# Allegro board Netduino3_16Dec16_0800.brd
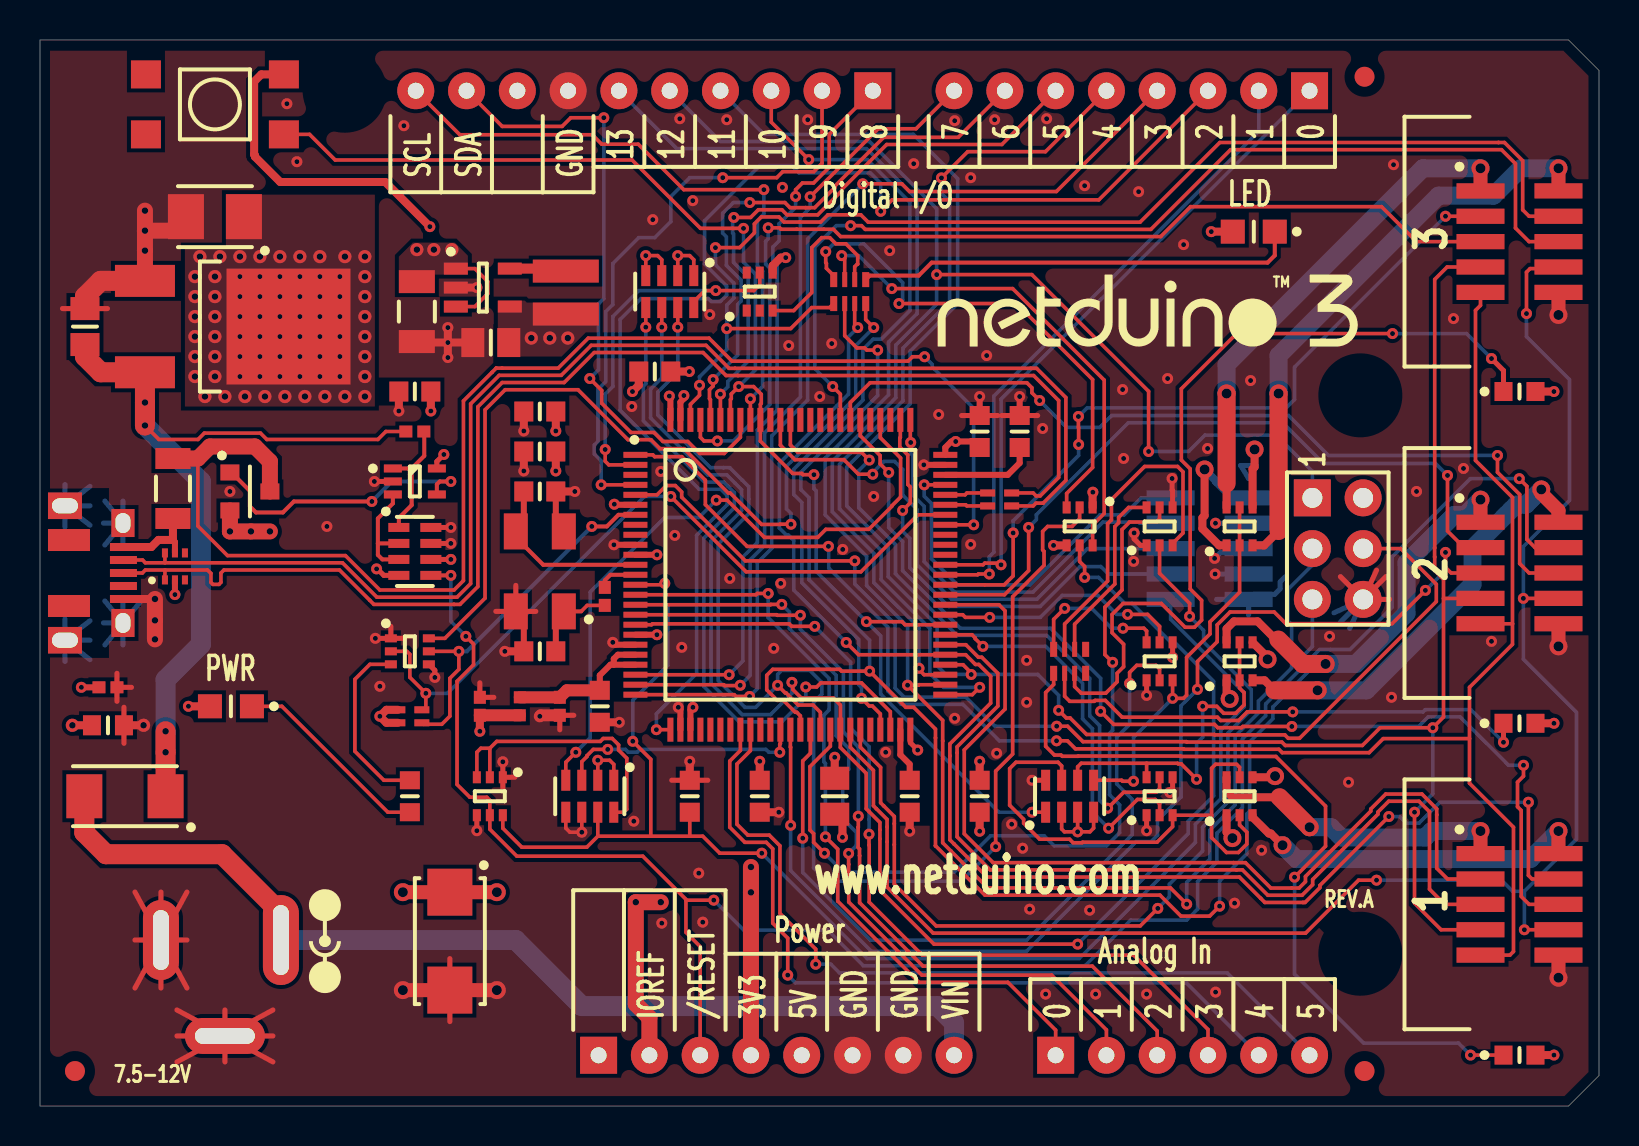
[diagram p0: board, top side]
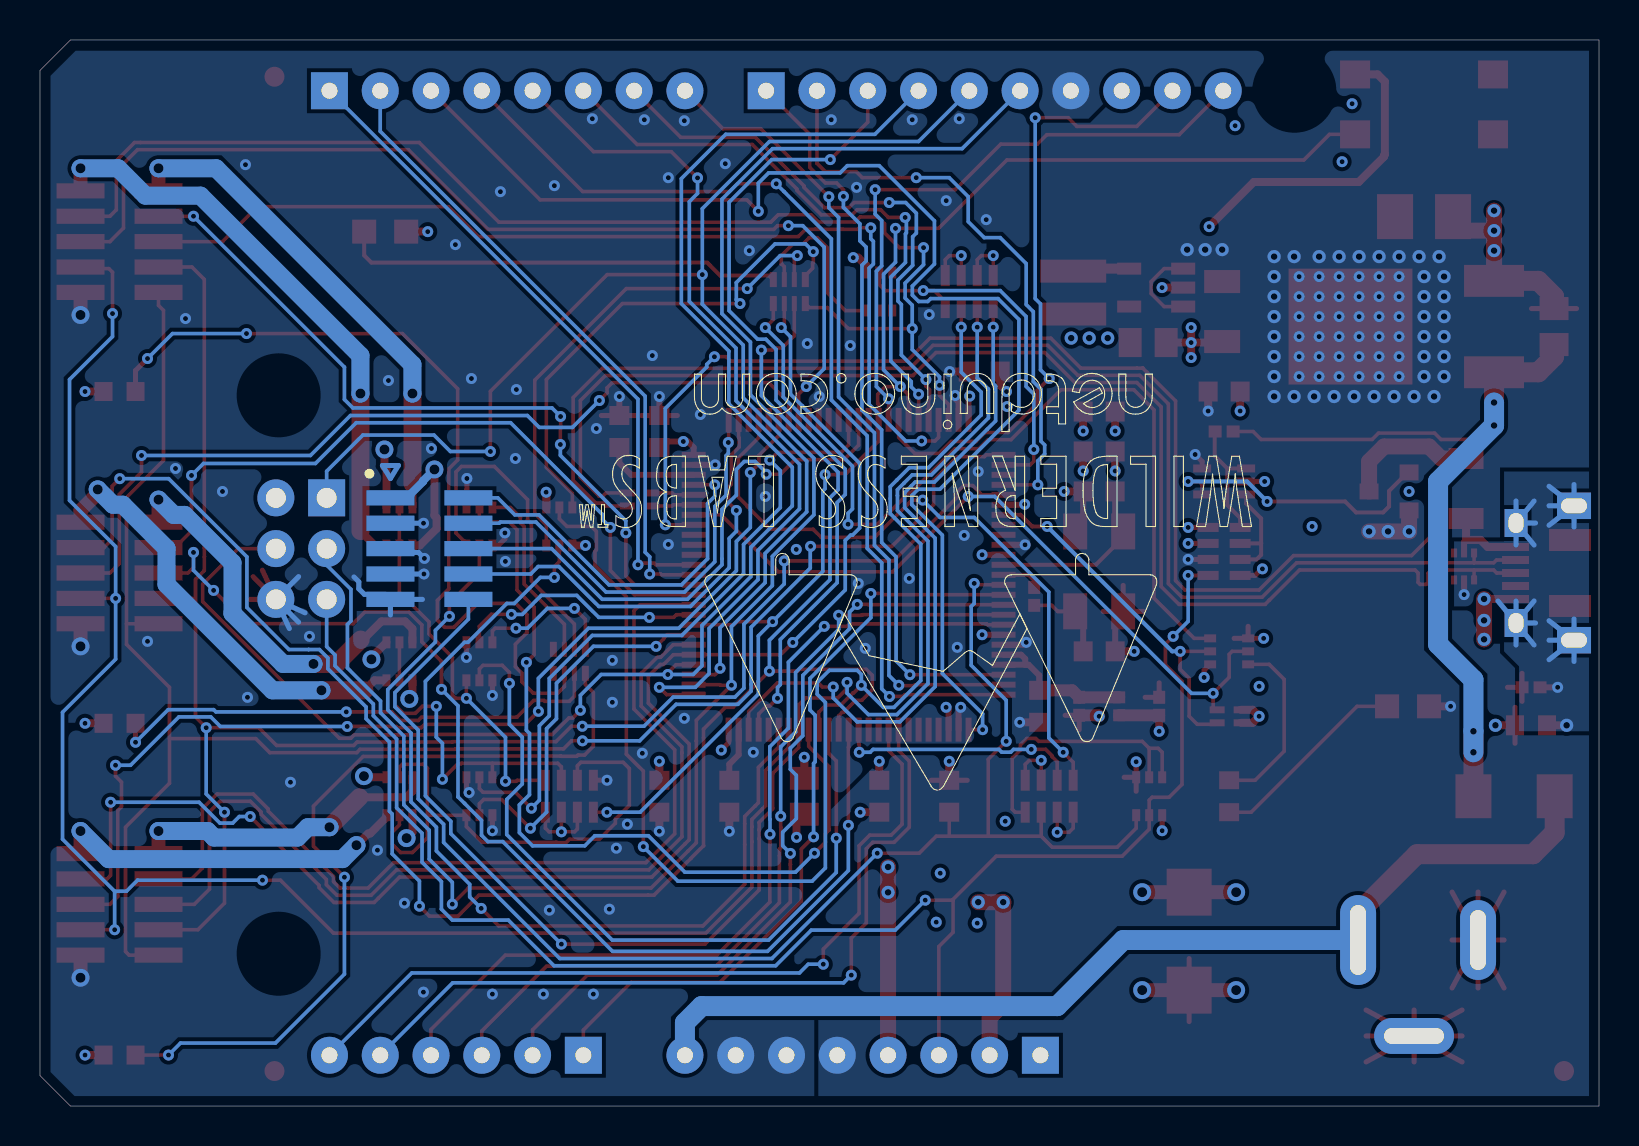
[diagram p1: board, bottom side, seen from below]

Outline 77.98 x 53.34 mm; copper layers: TOP, L2-GND, L3-PWR, BOTTOM. Coordinates in mm from the lower left corner of the outline.
Outline path: 0,0 0,53.34 76.45,53.34 77.98,51.82 77.98,1.52 76.45,0 0,0

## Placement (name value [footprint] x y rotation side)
C1  22uF  [CAPC3216X180N]  18.85 39.75 270 top
C2  10uF  [CAPC2012X125N]  2.25 39 90 top
C4  22uF  [CAPC2012X125N]  22.55 38.2 180 top
C5  0.1uF  [CAPC1608X90N]  28 20 270 top
C6  0.1uF  [CAPC1608X90N]  18.75 35.75 180 top
C10  0.1uF  [CAPC1608X90N]  25 32.75 180 top
C11  0.1uF  [CAPC1608X90N]  36 15.5 270 top
C12  0.1uF  [CAPC1608X90N]  47 15.5 270 top
C13  0.1uF  [CAPC1608X90N]  47 33.75 90 top
C14  0.1uF  [CAPC1608X90N]  30.75 36.75 0 top
C16  2.2uF  [CAPC1608X90N]  49 33.75 90 top
C17  2.2uF  [CAPC1608X90N]  43.5 15.5 270 top
C18  18pF  [CAPC1608X90N]  25 30.75 0 top
C19  18pF  [CAPC1608X90N]  25 22.75 180 top
C20  4.7nF  [CAPC1005X55N]  3.4 20.95 180 top
C21  100uF  [CAPMP6032X280N]  20.5 8.25 270 top
C42  22uF  [CAPC2012X125N]  39.75 15.5 270 top
C43  47uF  [F931A476MBA]  8.75 44.5 180 top
C44  1uF  [CAPC1005X55N]  26 20 270 top
C45  1uF  [CAPC1005X55N]  22 20 90 top
C46  0.1uF  [CAPC1608X90N]  25 34.75 180 top
C47  0.1uF  [CAPC1608X90N]  32.5 15.5 90 top
D1  WHITE  [LEDC2012X110N]  9.55 20 180 top
D2  BLUE  [LEDC2012X110N]  60.71 43.75 180 top
D3  SS15E-TP  [SS15-TP]  4.25 15.5 180 top
D4  -  [SP3003-04XTG]  6.75 27 90 top
D5  BLUE  [LEDC1608X80N]  74 2.55 0 top
D6  BLUE  [LEDC1608X80N]  74 19.15 0 top
D7  BLUE  [LEDC1608X80N]  74 35.75 0 top
F1  MF-NSMF075-2  [RESC3216X100N]  6.65 30.9 90 top
F2  -  [FID_1-00_X_2-00]  1.75 1.75 0 top
F3  -  [FID_1-00_X_2-00]  66.25 1.75 0 top
F4  -  [FID_1-00_X_2-00]  66.25 51.5 0 top
J1  ADC-043A-1  [ADC-002A-1]  -1.75 8.31 90 top
J2  HDR100IMP08F-G-V-TH-BLUE  [HDR100IMP08F-G-V-TH]  63.5 50.8 180 top
J3  HDR100IMP08F-G-V-TH-BLUE  [HDR100IMP10F-G-V-TH]  41.66 50.8 180 top
J4  HDR100IMP08F-G-V-TH-BLUE  [HDR100IMP06F-G-V-TH]  50.8 2.54 0 top
J5  -  [DX4R005JJ2R1800]  0 26.67 270 top
J6  HDR100IMP08F-G-V-TH-BLUE  [HDR100IMP08F-G-V-TH]  27.94 2.54 0 top
J7  -  [67996-206HLF]  63.64 30.43 270 top
J8  -  [MINI_JTAG_SMD]  58.5 27.89 180 bottom
J10  HDR050IDC10MS2-G-V-SM-BLUE  [20021521-00010T1LF]  74 10.09 0 top
J11  HDR050IDC10MS2-G-V-SM-BLUE  [20021521-00010T1LF]  74 26.67 0 top
J12  HDR050IDC10MS2-G-V-SM-BLUE  [20021521-00010T1LF]  74 43.25 0 top
L1  2.2uH  [LQH3NPN2R2NM0L]  26.3 40.7 270 top
L2  BEAD FERRITE/SM  [INDC1005X55N]  24 20 270 top
MT1  -  [MTG320H420NP_720KO]  15.24 50.8 0 top
MT2  -  [MTG320H420NP_720KO]  66.04 35.56 0 top
MT3  -  [MTG320H420NP_720KO]  66.04 7.62 0 top
NOREF  -  []  44.9 38 0 top
NOREF#2  -  []  14.25 8.25 90 top
NOREF#3  -  []  0 0 90 top
NOREF#4  -  []  0 53.34 0 top
Q1  -  [MUN5215DW1T1G]  18.5 22.75 0 top
Q2  -  [MUN5215DW1T1G]  22.5 15.5 270 top
Q3  -  [NTR4101PT1G]  10.5 30.75 0 top
Q4  -  [NTJD4152PT1G]  36 40.75 90 top
Q5  -  [NTJD4152PT1G]  60 15.5 90 top
Q6  -  [MUN5215DW1T1G]  56 15.5 90 top
Q7  -  [NTJD4152PT1G]  60 22.25 90 top
Q8  -  [NTJD4152PT1G]  52 29 270 top
Q9  -  [NTJD4152PT1G]  60 29 90 top
Q10  -  [MUN5215DW1T1G]  56 22.25 90 top
Q11  -  [MUN5215DW1T1G]  56 29 90 top
R1  1K  [RESCAV50P80X160X60-8N]  40.5 40.75 270 top
R3  1.5K  [RESC1608]  18.5 15.5 90 top
R4  10K  [RESCAV80P160X320X70-8N]  18.75 27.75 0 top
R5  10K  [RESCAV80P160X320X70-8N]  27.5 15.5 270 top
R6  15.4K  [CAPC1005X55N]  18.75 33.75 0 top
R7  390  [CAPC1005X55N]  28.25 25.5 90 top
R8  100K  [EXB24V]  18.5 19.5 0 top
R9  22  [EXB24V]  48 30.35 180 top
R10  1M  [RESC1608]  3.4 19.05 180 top
R12  10K  [RESCAV80P160X320X70-8N]  51.5 15.5 90 top
R14  10K  [RESCAV80P160X320X70-8N]  31.5 40.75 270 top
R15  680  [RESCAV50P80X160X60-8N]  51.5 22.25 90 top
SW1  -  [TSXH-2GL]  8.75 50.12 0 top
U1  LM3671MF-3.3/NOPB  [LM3671MF]  22.15 40.95 0 top
U2  -  [TLV1117-50IKVURG3]  5.25 39 0 top
U3  -  [LMV321IDCKR]  18.75 31.25 0 top
U4  STM32F427  [STM32F427VIT6]  37.53 26.58 0 top
Y1  25 Mhz  [ABM3B]  25 26.75 90 top

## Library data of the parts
C1 C2 C4-C6 C10-C14 C16-C21 C42-C47 = C
D1 = LED_2
D2 D5-D7 = LED_1
D3 = D05AZ75_0
D4 = HEADER 6_0
F1 = FUSE
F2-F4 MT1-MT3 = MOUNT_HOLE
J1 = HEADER 3
J2 J6 = HEADER 8
J3 = HEADER 10
J4 = HEADER 6
J5 = HEADER 11_0
J7 = HEADER 6_1
J8 J10-J12 = HEADER 10_2
L1 = L
L2 = BEAD FERRITE/SM
Q1 Q2 = MUN5215DW1T1G_3
Q3 = NDF0610/TO_1
Q4 Q5 Q7-Q9 = NTJD4152PT1G
Q6 Q10 Q11 = MUN5215DW1T1G_0
R1 R4 R5 R12 R14 R15 = RESCAV50P80X160X60-8N
R3 R6 R7 R10 = R
R8 R9 = EXB24V
SW1 = SW PUSHBUTTON-SPST-2_0
U1 = HEADER 5_0
U2 = LM7805/TO_2
U3 = LMV321/SO
U4 = STM32F427_0
Y1 = OSC_XF

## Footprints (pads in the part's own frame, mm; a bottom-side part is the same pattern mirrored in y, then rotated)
67996-206HLF
  rect 1.85x1.85 hole 1: 1(0,0)
  round 1.85 hole 1: 2(0,2.54) 3(2.54,0) 4(2.54,2.54) 5(5.08,0) 6(5.08,2.54)
20021521-00010T1LF
  rect 2.4x0.76 smd: 1(-1.95,2.54) 2(1.95,2.54) 3(-1.95,1.27) 4(1.95,1.27) 5(-1.95,0) 6(1.95,0) 7(-1.95,-1.27) 8(1.95,-1.27) 9(-1.95,-2.54) 10(1.95,-2.54)
ABM3B
  rect 1.8x1.2 smd: 1(-2,-1.2) 2(2,-1.2) 3(2,1.2) 4(-2,1.2)
ADC-002A-1
  oval 4.5x1.8 hole 3.5x0.8: 1(0,-13.8)
  oval 1.8x4 hole 0.8x3: 2(-4.8,-11)
  oval 4x1.8 hole 3x0.8: 3(0,-7.8)
CAPC1005X55N
  rect 0.65x0.6 smd: 1(-0.45,0) 2(0.45,0)
CAPC1608X90N
  rect 0.95x1 smd: 1(-0.8,0) 2(0.8,0)
CAPC2012X125N
  rect 1.15x1.45 smd: 1(-0.9,0) 2(0.9,0)
CAPC3216X180N
  rect 1.15x1.8 smd: 1(-1.5,0) 2(1.5,0)
CAPMP6032X280N
  rect 2.35x2.25 smd: 1(-2.45,0) 2(2.45,0)
DX4R005JJ2R1800
  rect 0.4x1.35 smd: 1(-1.3,4.175) 2(-0.65,4.175) 3(0,4.175) 4(0.65,4.175) 5(1.3,4.175)
  rect 1.4x1.15 hole 1x0.75: 6(-2.5,4.15) 7(2.5,4.15)
  rect 1.325x1.7 hole 0.75x1.3: 8(-3.362,1.25) 11(3.362,1.25)
  rect 1.1x2.1 smd: 9(-1.65,1.45) 10(1.65,1.45)
EXB24V
  rect 0.75x0.35 smd: 1(-0.6,0.325) 2(-0.6,-0.325) 3(0.6,-0.325) 4(0.6,0.325)
F931A476MBA
  rect 1.8x2.25 smd: 1(-1.45,0) 2(1.45,0)
FID_1-00_X_2-00
  round 1 smd: 1(0,0)
HDR100IMP06F-G-V-TH
  rect 1.85x1.85 hole 0.8: 1(0,0)
  round 1.85 hole 0.8: 2(2.54,0) 3(5.08,0) 4(7.62,0) 5(10.16,0) 6(12.7,0)
HDR100IMP08F-G-V-TH
  rect 1.85x1.85 hole 0.8: 1(0,0)
  round 1.85 hole 0.8: 2(2.54,0) 3(5.08,0) 4(7.62,0) 5(10.16,0) 6(12.7,0) 7(15.24,0) 8(17.78,0)
HDR100IMP10F-G-V-TH
  rect 1.85x1.85 hole 0.8: 1(0,0)
  round 1.85 hole 0.8: 2(2.54,0) 3(5.08,0) 4(7.62,0) 5(10.16,0) 6(12.7,0) 7(15.24,0) 8(17.78,0) 9(20.32,0) 10(22.86,0)
INDC1005X55N
  rect 0.6x0.6 smd: 1(-0.45,0) 2(0.45,0)
LEDC1608X80N
  rect 0.899x0.95 smd: A(0.8,0) C(-0.8,0)
LEDC2012X110N
  rect 1.2x1.2 smd: A(1.05,0) C(-1.05,0)
LM3671MF
  rect 1.2x0.6 smd: 1(-1.35,0.95) 2(-1.35,0) 3(-1.35,-0.95) 4(1.35,-0.95) 5(1.35,0.95)
LMV321IDCKR
  rect 0.9x0.4 smd: 1(-1.1,0.65) 2(-1.1,0) 3(-1.1,-0.65) 4(1.1,-0.65) 5(1.1,0.65)
LQH3NPN2R2NM0L
  rect 1.15x3.3 smd: 1(-1.075,0) 2(1.075,0)
MINI_JTAG_SMD
  rect 2.4x0.76 smd: 1(-1.95,2.54) 2(1.95,2.54) 3(-1.95,1.27) 4(1.95,1.27) 5(-1.95,0) 6(1.95,0) 7(-1.95,-1.27) 8(1.95,-1.27) 9(-1.95,-2.54) 10(1.95,-2.54)
MTG320H420NP_720KO
  round 0 hole 3.2 unplated: (0,0)
MUN5215DW1T1G
  rect 0.6x0.4 smd: 1(-0.95,0.65) 2(-0.95,0) 3(-0.95,-0.65) 4(0.95,-0.65) 5(0.95,0) 6(0.95,0.65)
NTJD4152PT1G
  rect 0.6x0.4 smd: 1(-0.95,0.65) 2(-0.95,0) 3(-0.95,-0.65) 4(0.95,-0.65) 5(0.95,0) 6(0.95,0.65)
NTR4101PT1G
  rect 0.95x0.8 smd: 1(-1,0.95) 2(-1,-0.95) 3(1,0)
RESC1608
  rect 0.899x1.001 smd: 1(-0.8,0) 2(0.8,0)
RESC3216X100N
  rect 1.05x1.75 smd: 1(-1.5,0) 2(1.5,0)
RESCAV50P80X160X60-8N
  rect 0.75x0.35 smd: 1(-0.6,0.8) 4(-0.6,-0.8) 5(0.6,-0.8) 8(0.6,0.8)
  rect 0.75x0.25 smd: 2(-0.6,0.25) 3(-0.6,-0.25) 6(0.6,-0.25) 7(0.6,0.25)
RESCAV80P160X320X70-8N
  rect 1.05x0.45 smd: 1(-0.8,1.2) 2(-0.8,0.4) 3(-0.8,-0.4) 4(-0.8,-1.2) 5(0.8,-1.2) 6(0.8,-0.4) 7(0.8,0.4) 8(0.8,1.2)
SP3003-04XTG
  rect 0.45x0.3 smd: 1(-0.675,0.5) 2(-0.675,0) 3(-0.675,-0.5) 4(0.675,-0.5) 5(0.675,0) 6(0.675,0.5)
SS15-TP
  rect 1.8x2.2 smd: A(2.032,0) C(-2.032,0)
STM32F427VIT6
  rect 1.2x0.3 smd: 1(-7.75,6) 2(-7.75,5.5) 3(-7.75,5) 4(-7.75,4.5) 5(-7.75,4) 6(-7.75,3.5) 7(-7.75,3) 8(-7.75,2.5) 9(-7.75,2) 10(-7.75,1.5) 11(-7.75,1) 12(-7.75,0.5) 13(-7.75,0) 14(-7.75,-0.5) 15(-7.75,-1) 16(-7.75,-1.5) 17(-7.75,-2) 18(-7.75,-2.5) 19(-7.75,-3) 20(-7.75,-3.5) 21(-7.75,-4) 22(-7.75,-4.5) 23(-7.75,-5) 24(-7.75,-5.5) 25(-7.75,-6) 51(7.75,-6) 52(7.75,-5.5) 53(7.75,-5) 54(7.75,-4.5) 55(7.75,-4) 56(7.75,-3.5) 57(7.75,-3) 58(7.75,-2.5) 59(7.75,-2) 60(7.75,-1.5) 61(7.75,-1) 62(7.75,-0.5) 63(7.75,0) 64(7.75,0.5) 65(7.75,1) 66(7.75,1.5) 67(7.75,2) 68(7.75,2.5) 69(7.75,3) 70(7.75,3.5) 71(7.75,4) 72(7.75,4.5) 73(7.75,5) 74(7.75,5.5) 75(7.75,6)
  rect 0.3x1.2 smd: 26(-6,-7.75) 27(-5.5,-7.75) 28(-5,-7.75) 29(-4.5,-7.75) 30(-4,-7.75) 31(-3.5,-7.75) 32(-3,-7.75) 33(-2.5,-7.75) 34(-2,-7.75) 35(-1.5,-7.75) 36(-1,-7.75) 37(-0.5,-7.75) 38(0,-7.75) 39(0.5,-7.75) 40(1,-7.75) 41(1.5,-7.75) 42(2,-7.75) 43(2.5,-7.75) 44(3,-7.75) 45(3.5,-7.75) 46(4,-7.75) 47(4.5,-7.75) 48(5,-7.75) 49(5.5,-7.75) 50(6,-7.75) 76(6,7.75) 77(5.5,7.75) 78(5,7.75) 79(4.5,7.75) 80(4,7.75) 81(3.5,7.75) 82(3,7.75) 83(2.5,7.75) 84(2,7.75) 85(1.5,7.75) 86(1,7.75) 87(0.5,7.75) 88(0,7.75) 89(-0.5,7.75) 90(-1,7.75) 91(-1.5,7.75) 92(-2,7.75) 93(-2.5,7.75) 94(-3,7.75) 95(-3.5,7.75) 96(-4,7.75) 97(-4.5,7.75) 98(-5,7.75) 99(-5.5,7.75) 100(-6,7.75)
TLV1117-50IKVURG3
  rect 3x1.6 smd: 1(0,2.286) 3(0,-2.286)
  rect 6.2x5.8 smd: 4(7.18,0)
TSXH-2GL
  rect 1.5x1.4 smd: 1(-3.45,1.5) 2(3.45,1.5) 3(-3.45,-1.5) 4(3.45,-1.5)

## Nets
3V3_GOPORT1: J10.1(3V3) Q5.6(DRAIN)
3V3_GOPORT2: J11.1(3V3) Q7.6(DRAIN)
3V3_GOPORT3: J12.1(3V3) Q9.6(DRAIN)
5V_GOPORT1: J10.2(5V) Q5.3(DRAIN)
5V_GOPORT2: J11.2(5V) Q7.3(DRAIN)
5V_GOPORT3: J12.2(5V) Q9.3(DRAIN)
+3.3V: C4.1 C10.1 C11.1 C12.1 C13.1 C14.1 C21.1 C42.1 C45.1 C46.1 J6.2 J6.4 J8.1(VCC) L1.2 L2.2 Q4.4(SOURCE) Q5.1(SOURCE) Q7.1(SOURCE) Q8.1(SOURCE) Q8.4(SOURCE) Q9.1(SOURCE) R4.4(1) R5.1 R5.2(1) R8.1 R8.2(1) R14.1 R14.2(1) R14.3(1) R14.4(1) SW1.2 U1.4(FB) U4.6(VBAT) U4.11(VDD1) U4.19(VDD2) U4.28(VDD3) U4.50(VDD4) U4.75(VDD5) U4.100(VDD6)
+5.0V: C1.1 C6.1 C43.1 D1.A(ANODE) D2.A(ANODE) D5.A(ANODE) D6.A(ANODE) D7.A(ANODE) J6.5 J7.2(VTG) Q3.2(SOURCE) Q5.4(SOURCE) Q7.4(SOURCE) Q9.4(SOURCE) R4.6(2) R12.2(1) R12.3(1) R12.4(1) U1.1(VIN) U1.3(EN) U2.4(VOUT) U3.5(+VCC)
+VIN: D3.A(1) J1.1 J6.8
+VIN_PROTECTED: C2.1 D3.C(2) R6.1 U2.3(VIN)
GND: C1.2 C2.2 C4.2 C5.2 C6.2 C10.2 C11.2 C12.2 C13.2 C14.2 C16.2 C17.2 C18.2 C19.2 C20.1 C21.2 C42.2 C43.2 C44.2 C45.2 C46.2 C47.2 J1.2 J1.3 J3.7 J5.5(GND) J6.6 J6.7 J7.6(GND) J8.3(GND1) J8.5(GND2) J8.7(GND3) J8.9(GND4) J10.10(GND) J11.10(GND) J12.10(GND) Q1.1(E) Q1.4(E) Q2.1(E) Q2.4(E) Q6.1(E) Q6.4(E) Q10.1(E) Q10.4(E) Q11.1(E) Q11.4(E) R4.7(2) R4.8(2) R5.5(2) R5.6(2) R10.1 R12.8(2) U1.2(GND) U2.1(GND) U3.2(-VCC) U4.10(VSS1) U4.20(VSSA) U4.27(VSS2) U4.74(VSS3) U4.99(VSS4) Y1.2 Y1.4
VIN_COMP_LOGIC: Q3.1(GATE) U3.4(OUT)
VIN_REF: R4.2(1) R4.3(1) U3.3(-VIN)
/ENABLE_UART_TX_PULLUP_GOPORT1: Q4.5(GATE) R14.8(2) U4.2(PE3)
/ENABLE_UART_TX_PULLUP_GOPORT2: Q8.2(GATE) R14.7(2) U4.41(PE10)
/ENABLE_UART_TX_PULLUP_GOPORT3: Q8.5(GATE) R14.6(2) U4.43(PE12)
/EXTERNAL_RESET: J6.3 J7.5(R\E\S\E\T\) Q2.5(B) R4.5(2)
/INT_GOPORT1: J10.3(GIPO) U4.60(PD13)
/INT_GOPORT2: J11.3(GIPO) U4.61(PD14)
/INT_GOPORT3: J12.3(GIPO) U4.62(PD15)
/PWR_CTRL_GOPORT1: Q5.2(GATE) Q5.5(GATE) Q6.3(C) R12.7(2)
/PWR_CTRL_GOPORT2: Q6.6(C) Q7.2(GATE) Q7.5(GATE) R12.6(2)
/PWR_CTRL_GOPORT3: Q9.2(GATE) Q9.5(GATE) Q10.3(C) R12.5(2)
/RESET_MCU: C47.1 J8.10(NRST) Q2.6(C) R5.7(2) U4.14(NRST)
/SPI_CS_GOPORT1: J10.6(SPI_CS) U4.81(PD0)
/SPI_CS_GOPORT2: J11.6(SPI_CS) U4.82(PD1)
/SPI_CS_GOPORT3: J12.6(SPI_CS) U4.83(PD2)
A0: J4.1 U4.15(PC0)
A1: J4.2 U4.16(PC1)
A2: J4.3 U4.17(PC2)
A3: J4.4 U4.18(PC3)
A4: J4.5 U4.33(PC4)
A5: J4.6 U4.34(PC5)
CHASSIS_USB: C20.2 D4.2(GND) J5.6(CHS1) J5.7(CHS2) J5.8(CHS3) J5.11(CHS4) R10.2
D0: J2.1 U4.64(PC7)
D1: J2.2 U4.63(PC6)
D2: J2.3 U4.26(PA3)
D3: J2.4 U4.25(PA2)
D4: J2.5 U4.51(PB12)
D5: J2.6 U4.95(PB8)
D6: J2.7 U4.96(PB9)
D7: J2.8 U4.24(PA1)
D8: J3.1 U4.23(PA0)
D9: J3.2 U4.4(PE5)
D10: J3.3 U4.47(PB10)
D11: J3.4 J7.4(MOSI) U4.54(PB15)
D12: J3.5 J7.1(MISO) U4.53(PB14)
D13: J3.6 J7.3(SCK) U4.52(PB13)
JTCK: J8.4(JTCK) U4.76(PA14)
JTDI: J8.8(JTDI) U4.77(PA15)
JTDO: J8.6(JTDO) U4.89(PB3)
JTMS: J8.2(JTMS) U4.72(PA13)
LED: Q1.2(B) R8.4(2) U4.69(PA10)
LED_GOPORT1: Q10.2(B) U4.40(PE9)
LED_GOPORT2: Q11.5(B) U4.42(PE11)
LED_GOPORT3: Q11.2(B) U4.45(PE14)
OSC_IN: C18.1 U4.12(PH0) Y1.3
OSC_OUT: R7.2 U4.13(PH1)
OTG_FS_DM: R9.4(2) U4.70(PA11)
OTG_FS_DP: R9.3(2) U4.71(PA12)
PWR_LED: Q1.5(B) R8.3(2) U4.7(PC13)
PWR_ON_GOPORT1: Q6.5(B) U4.88(PD7)
PWR_ON_GOPORT2: Q6.2(B) U4.57(PD10)
PWR_ON_GOPORT3: Q10.5(B) U4.59(PD12)
SCL: J3.10 U4.92(PB6)
SDA: J3.9 U4.93(PB7)
SPI3_MISO: R5.4(1) U4.79(PC11)
SPI4_MISO: J10.8(SPI_MISO) J11.8(SPI_MISO) J12.8(SPI_MISO) U4.44(PE13)
SPI4_MOSI: J10.7(SPI_MOSI) J11.7(SPI_MOSI) J12.7(SPI_MOSI) U4.5(PE6)
SPI4_SCK: J10.9(SPI_SCK) J11.9(SPI_SCK) J12.9(SPI_SCK) U4.1(PE2)
SWITCH1: R12.1 SW1.4 U4.58(PD11) U4.91(PB5) U4.94(BOOT0)
USART3_RX_GOPORT1: J10.5(USART_RX) U4.56(PD9)
USART3_TX_GOPORT1: J10.4(USART_TX) R1.7(2) U4.55(PD8)
USART7_RX_GOPORT2: J11.5(USART_RX) U4.38(PE7)
USART7_TX_GOPORT2: J11.4(USART_TX) R1.6(2) U4.39(PE8)
USART8_RX_GOPORT3: J12.5(USART_RX) U4.97(PE0)
USART8_TX_GOPORT3: J12.4(USART_TX) R1.5(2) U4.98(PE1)
USB5V: D4.5(VCC) F1.1 J5.1(VBUS)
USB5V_F: F1.2 Q3.3(DRAIN) U4.68(PA9)
USB_D+: D4.1(I/O1) J5.3(D+) R9.2(1)
USB_D-: D4.6(I/O4) J5.2(D-) R9.1
VCAP_1: C17.1 U4.49(VCAP_1)
VCAP_2: C16.1 U4.73(VCAP_2)
N62667: R4.1 R6.2 U3.1(+VIN)
N62753: Q2.2(B) Q2.3(C) R5.8(2)
N62779: L1.1 U1.5(SW)
N62801: D2.C(CATHODE) R1.1
N62841: R5.3(1) U4.37(PB2)
N63081: C5.1 C44.1 L2.1 U4.21(VREF+) U4.22(VDDA)
N74908: Q1.6(C) R1.8(2)
N77511: D1.C(CATHODE) R3.1
N77515: Q1.3(C) R3.2
N197515: Q10.6(C) R15.8(2)
N197535: D5.C(CATHODE) R15.1
N197921: Q11.3(C) R15.7(2)
N197949: D6.C(CATHODE) R15.2(1)
N198166: Q11.6(C) R15.6(2)
N198194: D7.C(CATHODE) R15.3(1)
N199051: Q4.3(DRAIN) R1.2(1)
N202411: Q8.6(DRAIN) R1.3(1)
N203046: Q8.3(DRAIN) R1.4(1)
N249435: R14.5(2) U4.48(PB11)
N261857: C19.1 R7.1 Y1.1

Pads without a net: D4 3 4; F2 1; F3 1; F4 1; J3 8; J5 4 9 10; J6 1; Q4 1 2 6; R15 4 5; SW1 1 3; U4 3 8 9 29 30 31 32 35 36 46 65 66 67 78 80 84 85 86 87 90

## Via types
v1: diameter 0.55, hole 0.25, TOP to BOTTOM, 333 vias
v2: diameter 0.9, hole 0.5, TOP to BOTTOM, 25 vias
v3: diameter 0.66, hole 0.33, TOP to BOTTOM, 61 vias

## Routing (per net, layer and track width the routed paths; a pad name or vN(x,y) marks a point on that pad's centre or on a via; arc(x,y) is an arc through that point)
3V3_GOPORT1: length 15.6
  TOP w0.4: 62,15.45 59.65,15.45 59.35,15.75 Q5.6
  TOP w0.7: J10.1 v2(72.05,13.76)
  TOP w0.9: 62,15.45 v2(63.5,13.95)
  BOTTOM w0.9: v2(63.5,13.95) 64.58,13.95 65.09,13.44 69.27,13.44 69.6,13.76 v2(72.05,13.76)
3V3_GOPORT2: length 20.4
  TOP w0.4: 61.94,23.34 61.81,23.34 60.9,24.25 59.72,24.25 59.35,23.88 Q7.6
  TOP w0.7: J11.1 v2(72.05,30.34)
  TOP w0.9: 61.94,23.34 63.16,22.12 v2(64.3,22.12)
  BOTTOM w0.9: v2(72.05,30.34) 71.29,29.58 70.74,29.58 68.35,27.18 68.35,24.65 65.82,22.12 v2(64.3,22.12)
3V3_GOPORT3: length 25
  TOP w0.4: 59.35,31.15 Q9.6
  TOP w0.7: J12.1 v2(72.05,46.92)
  TOP w0.9: v2(59.35,35.65) 59.35,31.15
  BOTTOM w0.9: v2(72.05,46.92) 69.17,46.92 59.35,37.1 v2(59.35,35.65)
5V_GOPORT1: length 18
  TOP w0.4: v2(62.15,13.05) 61.56,13.64 61.46,13.64 60.65,14.45 Q5.3
  TOP w0.7: J10.2 v2(75.95,13.76)
  BOTTOM w0.9: v2(75.95,13.76) 74.55,12.36 62.84,12.36 v2(62.15,13.05)
5V_GOPORT2: length 21.9
  TOP w0.4: 61.75,20.8 61.25,21.3 Q7.3
  TOP w0.7: J11.2 75.95,29.8 75.09,30.66 v2(75.09,30.85)
  TOP w0.9: 61.75,20.8 v2(63.9,20.8)
  BOTTOM w0.9: v2(63.9,20.8) 66.35,20.8 71.65,26.1 71.65,27.9 73.84,30.09 74.33,30.09 v2(75.09,30.85)
5V_GOPORT3: length 29.4
  TOP w0.4: 61.95,28.77 61.23,28.05 Q9.3
  TOP w0.7: J12.2 v2(75.95,46.92)
  TOP w0.9: v2(61.95,35.65) 61.95,28.77
  BOTTOM w0.9: v2(75.95,46.92) 74.07,46.92 72.7,45.55 69.95,45.55 61.95,37.55 v2(61.95,35.65)
+3.3V: length 80.4
  TOP w0.18: R14.3 31.1,42.34 30.89,42.55 v1(30.3,42.55) R14.4 ; R5.2 v1(27.9,17.3) 28.5,17.3 28.7,17.09 R5.1 ; R14.2 v1(31.9,42.55) 32.49,42.55 32.7,42.34 R14.1
  TOP w0.25: R4.4 17.2,26.55 16.87,26.88 v1(16.84,26.88) ; v1(43.9,17.81) 43.53,18.18 U4.50
  TOP w0.3: U4.100 31.53,35.47 v1(31.48,35.52) ; v1(28.73,30.11) 28.76,30.08 U4.6 ; U4.19 v1(30.86,23.58) ; U4.28 32.53,19.82 v1(32.66,19.95) ; C13.1 46.7,33.25 v1(45.8,33.25) 45.58,33.25 45.28,32.95 U4.75 ; U4.11 v1(30.86,27.58)
  TOP w0.4: Q9.1 58.98,28.05 58.14,28.89 58.14,29.43 58.25,29.54 v2(58.25,31.85) ; v1(19.5,44) 17.27,46.23 12.02,46.23 10.75,47.5 10.75,47.57 10.71,47.61 10.71,51.26 11.07,51.62 SW1.2 ; R8.1 17.32,19.82 v1(17,19.5) 17.32,19.18 R8.2 ; C42.1 v1(39.75,17.45) ; C45.1 v1(22,18.75) ; C11.1 v1(36,17.25) ; Q7.1 59.35,20.52 v2(59.5,20.37) ; v1(37.3,42.45) 37.05,42.45 36.65,42.05 Q4.4 ; C10.1 v1(25.8,31.77) ; v1(52.66,30.71) 52.65,30.7 Q8.1 ; C46.1 v1(25.8,33.77) ; C12.1 v1(47,17.25) ; Q5.1 59.35,13.7 v2(59.64,13.41) ; C14.1 29.95,36.06 v1(29.64,35.75) ; Q8.4 v1(50.7,28.05)
  TOP w0.6: L2.2 C45.1
  TOP w0.7: v2(18.15,10.7) C21.1 v2(22.85,10.7)
  TOP w0.8: v3(35.56,11.96) v3(35.56,10.69) J6.4 ; J6.2 30.48,4.42 29.8,5.1 v3(29.8,10.2) v3(31.05,10.2)
  BOTTOM w0.4: J8.1 59.63,30.43 58.82,31.24 58.82,31.28 v2(58.25,31.85)
  vias: v3(24.57,38.42) v3(25.5,38.42) v3(26.4,38.42)
+5.0V: length 33.8
  TOP w0.18: U1.3 21.75,40 22.4,40.65 22.4,41.25 21.75,41.9 U1.1 ; R12.4 52.7,13.9 52.52,13.72 v1(51.9,13.72) ; v1(51.9,13.72) 51.24,13.72 51.1,13.86 R12.2 ; v1(51.9,13.72) R12.3
  TOP w0.25: U3.5 19.85,32.25 v1(20.2,32.6) ; R4.6 v1(20.55,27.35)
  TOP w0.4: D7.A v1(75.72,35.75) ; D5.A v1(75.72,2.55) ; D2.A v1(58.59,43.75) ; v2(61.77,16.51) 61.72,16.45 Q5.4 ; D1.A v1(7.42,20) ; Q7.4 61.4,22.45 v2(61.4,22.35) ; D6.A v1(75.72,19.15) ; v2(60.75,32.85) 60.75,31.97 60.65,31.87 Q9.4 ; C6.1 v1(19.55,34.77)
  TOP w0.8: Q3.2 v3(9.5,28.75) v3(10.55,28.75) v3(11.5,28.75)
  L3-PWR w0.254: J7.2 67.5,30.43 ; J7.2 66.18,31.75 ; J7.2 67.32,31.57 ; J7.2 67.32,29.29 ; J7.2 65.04,31.57 ; J7.2 65.04,29.29
  vias: v1(10,41.5) v1(10,40.5) v1(10,39.5) v1(10,38.5) v1(10,37.5) v1(10,36.5) v1(11,41.5) v1(11,40.5) v1(11,39.5) v1(11,38.5) v1(11,37.5) v1(11,36.5) v1(12,41.5) v1(12,40.5) v1(12,39.5) v1(12,38.5) v1(12,37.5) v1(12,36.5) v1(13,41.5) v1(13,40.5) v1(13,39.5) v1(13,38.5) v1(13,37.5) v1(13,36.5) v1(14,41.5) v1(14,40.5) v1(14,39.5) v1(14,38.5) v1(14,37.5) v1(14,36.5) v1(15,41.5) v1(15,40.5) v1(15,39.5) v1(15,38.5) v1(15,37.5) v1(15,36.5) v3(7.75,41.5) v3(7.75,40.5) v3(7.75,39.5) v3(7.75,38.5) v3(7.75,37.5) v3(7.75,36.5) v3(8,42.5) v3(8.25,35.5) v3(8.75,41.5) v3(8.75,40.5) v3(8.75,39.5) v3(8.75,38.5) v3(8.75,37.5) v3(8.75,36.5) v3(9,42.5) v3(9.25,35.5) v3(10,42.5) v3(10.25,35.5) v3(11,42.5) v3(11.25,35.5) v3(12,42.5) v3(12.25,35.5) v3(13,42.5) v3(13.25,35.5) v3(14,42.5) v3(14.25,35.5) v3(15.25,42.5) v3(15.25,35.5) v3(16.25,42.5) v3(16.25,41.5) v3(16.25,40.5) v3(16.25,39.5) v3(16.25,38.5) v3(16.25,37.5) v3(16.25,36.5) v3(16.25,35.5) v3(18.85,42.85) v3(19.7,42.85) v3(20.6,42.85)
+VIN: length 51.7
  TOP w1: J1.1 12.05,9.66 9.11,12.6 3.3,12.6 2.22,13.68 D3.A
  BOTTOM w1: J6.8 45.72,4.17 44.88,5 27.1,5 23.79,8.31 J1.1
+VIN_PROTECTED: length 43
  TOP w0.18: R6.1 17.3,33.75 16.9,33.35 11.35,33.35 11.03,33.67 8.22,33.67 7.9,33.35 5.95,33.35 v3(5.25,34.05)
  TOP w1: v3(5.25,34.05) v3(5.25,35.2) U2.3 3.04,36.71 2.25,37.5 C2.1 ; v3(6.28,18.75) v3(6.28,17.7) D3.C
  BOTTOM w1: v3(6.28,17.7) v3(6.28,18.75) 6.28,21.33 8.05,23.1 8.05,31.25 v3(5.25,34.05) v3(5.25,35.2)
GND: length 196.2
  TOP w0.18: R5.5 26.3,13.9 26.5,13.7 v1(27.1,13.7) R5.6
  TOP w0.25: v1(56.62,31.4) 56.62,30.82 56.65,30.79 Q11.4 ; Q2.4 v1(21.85,13.78) ; Q2.1 v1(23.15,17.23) ; R4.8 v1(20.55,28.95) ; v1(56.52,15.69) 56.65,15.82 Q6.4 ; Q6.1 v1(55.35,13.78) ; Q1.4 19.75,21.8 v1(19.75,21.45) ; v1(54.73,28.68) 54.73,28.38 55.05,28.05 Q11.1 ; R12.8 v1(49.62,16.3) ; R4.7 v1(20.55,28.15) ; Q10.4 v1(56.65,22.45) ; U3.2 v1(16.73,31.25) ; Q1.1 v1(16.77,23.4) ; Q10.1 v1(55.35,20.55)
  TOP w0.254: 4.75,8.31 J1.3 ; J1.3 7.35,10.71 ; J1.3 6.05,5.91 ; J1.3 6.05,10.71 ; J1.3 7.35,8.31 ; J1.3 7.35,5.91 ; J1.3 4.75,10.71 ; J1.3 4.75,5.91 ; 6.85,2.21 J1.2 ; J1.2 11.65,3.51 ; J1.2 6.85,4.81 ; J1.2 9.25,2.21 ; J1.2 9.25,4.81 ; J1.2 11.65,4.81 ; J1.2 6.85,3.51 ; J1.2 11.65,2.21 ; 4.2,19.95 R10.1 4.2,18.15 ; 3.85,20.25 C20.1 ; C20.1 4.57,20.95 ; C20.1 3.85,21.65 ; 18.25,23.4 Q1.1 17.55,24 ; 23.75,16.45 Q2.1 23.15,15.75 ; 48.1,34.55 C16.2 49.9,34.55 ; 31.6,16.3 C47.2 33.4,16.3 ; J7.6 67.32,26.49 ; J7.6 65.04,26.49 ; J7.6 67.5,25.35 ; J7.6 66.85,26.81 ; Y1.4 24.8,24.75 ; Y1.4 23.8,26.05 ; Y1.4 22.8,24.75 ; 20.5,4.23 C21.2 20.5,7.37 ; 1.13,39.9 C2.2 3.37,39.9 ; 47.9,34.55 C13.2 46.1,34.55 ; 22.7,20.45 C45.2 22,21.17 ; 26,18.83 C44.2 26.7,19.55
  TOP w0.3: C13.2 v1(47,35.5) ; U4.20 28.77,23.08 v1(28.65,23.2) ; C16.2 v1(49,35.5) ; Y1.2 25.8,29.15 C18.2 ; v1(31.93,19.95) 32.03,19.84 U4.27 ; Y1.4 24.2,24.35 C19.2 ; U4.10 v1(28.71,28.08) ; U4.74 v1(44.21,32.08) ; v1(32.21,35.55) 32.21,35.4 32.03,35.22 U4.99
  TOP w0.4: C12.2 v1(47,13.75) ; v1(20.4,38.2) v1(20.4,38.95) ; v1(20.4,38.2) 18.9,38.2 C1.2 ; v1(20.4,38.2) C4.2 ; v1(20.4,38.2) v1(20.4,37.45) ; v1(40.14,13.45) 40.14,14.21 C42.2 ; U1.2 v1(21.86,40.95) ; C5.2 v1(28.98,19.2) ; C14.2 v1(32.48,36.75) ; C19.2 v1(23.25,22.75) ; J5.5 v3(5.75,25.37) ; C10.2 v1(24.2,31.77) ; C18.2 v1(26.75,30.75) ; C11.2 v1(36.95,14.7) ; R10.1 v3(5.18,19.05) ; C46.2 v1(24.2,33.77) ; C6.2 v1(17.95,34.77) ; C47.2 v1(32.5,17.25) ; C17.2 v1(43.5,13.75)
  TOP w0.6: C44.2 25.05,19.55 v1(25,19.5)
  TOP w0.7: J10.10 v2(75.95,6.42) ; J12.10 v2(75.95,39.58) ; v2(22.85,5.8) C21.2 v2(18.15,5.8) ; J11.10 v2(75.95,23)
  TOP w0.8: v3(5.25,43.8) v3(5.25,44.8) ; v3(5.25,43.8) v3(5.25,42.8) U2.1 ; v3(5.25,43.8) 6.6,43.8 C43.2 ; v3(5.75,25.37) v3(5.75,24.3) v3(5.75,23.35)
  TOP w1: C2.2 2.25,40.5 3.04,41.29 U2.1
  L2-GND w0.254: J7.6 67.5,25.35 ; J7.6 66.18,24.03 ; J7.6 67.32,24.21 ; J7.6 65.04,26.49 ; J7.6 67.32,26.49 ; J7.6 65.04,24.21 ; J1.3 7.35,8.31 ; J1.3 4.75,10.71 ; J1.3 6.05,10.71 ; J1.3 6.05,5.91 ; J1.3 7.35,5.91 ; J1.3 4.75,5.91 ; J1.3 4.75,8.31 ; J1.3 7.35,10.71 ; J1.2 11.65,3.51 ; J1.2 11.65,4.81 ; J1.2 9.25,2.21 ; J1.2 11.65,2.21 ; J1.2 9.25,4.81 ; J1.2 6.85,4.81 ; J1.2 6.85,2.21 ; J1.2 6.85,3.51
  BOTTOM w0.25: J8.7 v1(58.77,26.62) ; v1(58.75,27.4) 59.05,27.7 60.26,27.7 J8.5 ; 62.28,26.47 62.03,26.23 62.03,25.88 61.75,25.6 60.7,25.6 J8.9 ; J8.3 v1(58.8,29.16)
  BOTTOM w0.254: 60.45,24.57 J8.9 58.85,25.35 ; 65.04,24.21 J7.6 ; J7.6 65.04,26.49 ; J7.6 65.51,23.89 ; J7.6 64.72,24.68
  vias: v1(9.5,30.75) v1(12.35,50.15) v1(12.85,47.25) v1(14.35,29) v1(17,21) v1(18.2,49.05) v1(29.6,35) v1(29.7,14.25) v1(30.65,44.35) v1(31.05,31.75) v1(31.1,9.15) v1(31.75,28.55) v1(32,49.4) v1(32.1,22.95) v1(32.65,45.3) v1(32.95,11.65) v1(33.15,9.2) v1(33.5,39.6) v1(34.35,49.35) v1(34.5,26.4) v1(36.7,22.9) v1(37.05,26.15) v1(37.14,45.96) v1(37.45,38.05) v1(38.4,49.35) v1(39,35.5) v1(39.6,38.15) v1(40.15,27.85) v1(41.7,30.5) v1(42.3,17.7) v1(42.5,42.8) v1(43.7,47.15) v1(44.95,34.6) v1(45.75,49.3) v1(45.75,19.4) v1(46.55,46.45) v1(46.55,28.1) v1(47.35,37.55) v1(47.75,49.35) v1(47.85,17.65) v1(48.6,14.1) v1(49.15,12.9) v1(49.35,22.3) v1(49.35,20.2) v1(49.5,9.85) v1(50.15,33.9) v1(50.3,5.6) v1(50.35,49.4) v1(52.25,46.05) v1(52.5,9.8) v1(52.8,5.6) v1(54.15,35.85) v1(54.2,32.4) v1(54.7,27.25) v1(54.95,45.75) v1(55.35,5.6) v1(56.4,36.4) v1(57.2,43.1) v1(58.4,32.9) v1(58.8,5.7) v1(59.75,10.15) v1(60.55,36.3) v1(61.1,12.8) v1(64.5,23.5) v1(65.45,16.2) v1(67.6,20.45) v1(67.7,47.1) v1(68.85,30.75) v1(70.7,39.4) v1(71.2,31.9) v1(72.6,23.25)
VIN_COMP_LOGIC: length 14.2
  TOP w0.2: Q3.1 9.57,31.7 10.5,30.77 10.5,30 10.8,29.7 12.15,29.7 12.7,30.25 v1(16.6,30.25) ; U3.4 19.85,31.11 20,31.25 v1(20.55,31.25)
  BOTTOM w0.2: v1(16.6,30.25) 17.6,31.25 v1(20.55,31.25)
VIN_REF: length 5.5
  TOP w0.2: U3.3 17.65,30.15 16.9,29.4 16.9,28.15 ; R4.2 16.9,28.15 ; 16.9,28.15 16.9,27.57 17.12,27.35 R4.3
/ENABLE_UART_TX_PULLUP_GOPORT1: length 19.2
  TOP w0.18: R14.8 32.7,40.25 33.25,40.8 v1(33.8,40.8) 35.7,40.8 36,41.1 Q4.5 ; U4.2 28.45,32.08 28.27,32.26 v1(28.27,32.85)
  BOTTOM w0.18: v1(33.8,40.8) 29.95,40.8 28.66,39.51 28.66,36.01 28.27,35.62 v1(28.27,32.85)
/ENABLE_UART_TX_PULLUP_GOPORT2: length 71.8
  TOP w0.18: Q8.2 52,29.38 51.62,29 50.4,29 50.15,28.75 50.15,27.82 50.22,27.75 50.22,27.05 48.65,25.48 48.65,17.61 47.8,16.76 v1(47.8,12.98) ; v1(31.9,38.97) R14.7 ; v1(36.9,21.05) 37.28,20.66 37.32,20.66 37.93,20.06 38.67,20.06 39.03,19.7 U4.41
  BOTTOM w0.18: v1(47.8,12.98) 46.07,11.25 39.36,11.25 38.7,11.91 38.7,20.2 39.1,20.6 39.1,21.2 38.5,21.8 37.1,21.8 36.9,21.59 v1(36.9,21.05) 35.79,19.95 35.27,19.95 33.92,21.29 33.92,28.11 35.24,29.43 35.45,29.64 35.45,30.39 35.45,30.99 35.13,31.31 34.5,31.94 34.2,31.94 33.54,31.94 30.9,34.58 30.9,35.72 31.9,36.72 v1(31.9,38.97)
/ENABLE_UART_TX_PULLUP_GOPORT3: length 78.2
  TOP w0.18: v1(37.61,21.2) 37.66,21.15 37.66,20.84 38.08,20.42 39.68,20.42 40.03,20.07 U4.43 40.03,17.94 41.33,16.64 41.33,14.88 41.48,14.73 41.48,14.72 42.01,14.19 42.01,13.83 42.01,10.8 44.72,8.1 v1(51.9,8.1) ; v1(52.25,26.45) 52.25,27 52,27.25 Q8.5 ; R14.6 v1(31.1,38.97)
  BOTTOM w0.18: v1(52.25,26.45) 52.95,26.45 54.26,25.14 54.63,25.14 56.57,23.2 56.75,23.2 58.7,21.25 58.7,15.52 57.43,14.25 57.43,13.63 v1(51.9,8.1) ; v1(37.61,21.2) 37.61,20.65 36.54,19.59 35.12,19.59 33.56,21.14 33.56,28.26 35.09,29.79 35.09,30.54 35.09,30.84 34.77,31.16 34.35,31.58 33.39,31.58 30.54,34.43 30.54,35.87 31.1,36.43 v1(31.1,38.97)
/EXTERNAL_RESET: length 81
  TOP w0.18: 32.31,10.3 32.31,10.34 30.15,12.5 23.85,12.5 22.5,13.85 Q2.5 22.5,15.3 22.35,15.45 21.5,15.45 20.86,16.09 20.86,21.25 21.69,22.08 21.69,23.11 v1(21.3,23.5) ; 32.31,10.3 32.31,8.69 33.02,7.98 J6.3 ; 32.31,10.3 v1(33.7,10.3)
  TOP w0.2: R4.5 v1(20.55,26.55)
  BOTTOM w0.18: v1(20.55,26.55) 20.55,24.25 v1(21.3,23.5) ; J7.5 63.64,22.99 63.22,22.57 63.22,22.03 61.3,20.11 61.3,19.53 60.14,18.36 60.14,14.92 58.87,13.65 58.87,12.2 57.9,11.23 57.9,9.85 57.35,9.3 54.55,9.3 52.27,7.02 41.18,7.02 39.4,8.8 35.2,8.8 v1(33.7,10.3)
/INT_GOPORT1: length 47.7
  TOP w0.18: J10.3 70.4,11.36 69.86,11.9 69.86,14.57 69.86,14.87 69.12,15.61 67.31,15.61 66.56,14.86 66.56,14.75 63.3,11.49 63.3,11.22 62.98,10.91 62.61,10.91 62.6,10.9 61.56,10.9 60.29,12.18 59.7,12.18 47.67,12.18 46.23,13.62 46.23,17.82 48.27,19.86 48.27,24.78 47.97,25.08 U4.60
/INT_GOPORT2: length 36
  TOP w0.18: U4.61 48.24,25.58 49.45,26.79 v1(49.45,28.95) ; v1(70.4,31.55) 70.4,28.77 71.23,27.94 J11.3
  BOTTOM w0.18: v1(70.4,31.55) 69.8,32.15 64.2,32.15 62.16,34.19 54.44,34.19 49.84,29.59 49.84,29.34 v1(49.45,28.95)
/INT_GOPORT3: length 38.1
  TOP w0.18: v1(48.67,28.67) 48.67,26.52 48.23,26.07 47.26,26.07 47.25,26.08 U4.62 ; v1(51.95,33.1) 51.95,33.95 51.94,33.95 v1(51.94,34.5) ; J12.3 v1(70.3,44.52)
  BOTTOM w0.18: v1(70.3,44.52) 62.75,36.97 62.75,35.35 62.33,34.93 52.37,34.93 v1(51.94,34.5) ; v1(51.95,33.1) 51.95,32.55 48.67,29.28 v1(48.67,28.67)
/PWR_CTRL_GOPORT1: length 26.6
  TOP w0.18: 58.6,14.55 Q6.3 56.65,13.98 55.87,13.2 52.15,13.2 52.13,13.18 51.67,13.18 51.5,13.35 50,13.35 49.2,14.15 49.2,14.35 48.5,15.05 48.5,16.89 48.81,17.2 50.92,17.2 51.1,17.02 R12.7 ; 58.6,14.55 58.6,16.9 58.8,17.1 59.85,17.1 60,16.95 Q5.5 ; 58.6,14.55 58.6,13.43 59.34,12.69 59.94,12.69 60.36,13.11 60.36,13.7 60,14.07 Q5.2
/PWR_CTRL_GOPORT2: length 17.1
  TOP w0.18: R12.6 51.9,16.97 52.08,17.15 55.35,17.15 ; v1(57.85,16.35) 57.08,17.12 56.93,17.12 56.9,17.15 55.35,17.15 ; 55.35,17.15 Q6.6 ; v1(58.16,20) 58.86,20 59.21,19.65 59.8,19.65 60.22,20.07 60.22,20.68 60,20.91 Q7.2 Q7.5
  BOTTOM w0.18: v1(57.85,16.35) 57.85,18.15 58.16,18.45 v1(58.16,20)
/PWR_CTRL_GOPORT3: length 19.1
  TOP w0.18: Q10.3 v1(56.65,20.4) 57.2,20.4 57.35,20.55 57.35,22.45 58.52,23.62 58.52,24.22 60,25.7 Q9.2 Q9.5 ; R12.5 54.1,16.3 54.15,16.25 v1(54.7,16.25)
  BOTTOM w0.18: v1(56.65,20.4) 54.7,18.45 v1(54.7,16.25)
/RESET_MCU: length 73.3
  TOP w0.18: 30.55,13.5 32.5,13.5 ; 30.55,13.5 30.55,17.35 v1(29.65,18.25) ; 30.55,13.5 27.9,13.5 ; 32.5,13.5 33.15,13.5 34,12.65 v1(36.1,12.65) ; 32.5,13.5 C47.1 ; U4.14 31.18,26.08 v1(31.25,26.15) ; 27.9,13.5 R5.7 ; 27.9,13.5 27.35,12.95 24.1,12.95 23.15,13.9 Q2.6
  BOTTOM w0.18: v1(31.25,26.15) 31.25,25.15 31.4,25 31.4,22.05 29.65,20.3 v1(29.65,18.25) ; J8.10 56.55,24.36 60.22,20.68 60.22,19.97 59.06,18.81 59.06,15.37 57.79,14.1 57.79,13.19 51.98,7.38 41.37,7.38 v1(36.1,12.65)
/SPI_CS_GOPORT1: length 53.7
  TOP w0.18: v1(74.2,17.05) 74.2,16.5 73.9,16.21 73.9,14.97 74.09,14.79 74.09,10.48 74.48,10.09 J10.6 ; v1(62.61,18.99) 60.16,18.99 60.1,18.93 58.91,18.93 58.74,19.09 53.7,19.09 v1(53.05,19.75) ; U4.81 41.03,33.54 42.02,32.55 42.02,32.13 v1(42.45,31.7)
  BOTTOM w0.18: v1(74.2,17.05) 73.45,17.05 71.03,19.47 69.44,19.47 68.96,18.99 v1(62.61,18.99) ; v1(53.05,19.75) 53.05,21.4 50.55,23.91 46.03,23.91 43.15,26.78 43.15,28.25 42.45,28.95 v1(42.45,31.7)
/SPI_CS_GOPORT2: length 43.8
  TOP w0.18: U4.82 40.53,35.2 41.52,36.19 49.36,36.19 49.61,35.94 49.61,35.69 v1(50,35.3) ; v1(72.9,32.55) 72.9,31.71 74.01,30.6 74.01,27.14 74.48,26.67 J11.6
  BOTTOM w0.18: v1(72.9,32.55) 64.45,32.55 62.45,34.55 53.6,34.55 53.01,33.95 51.34,33.95 v1(50,35.3)
/SPI_CS_GOPORT3: length 52.3
  TOP w0.18: v1(39.65,36) 40.03,35.62 U4.83 ; J12.6 74.48,43.25 73.8,43.93 73.8,47.15 73.1,47.85 59.55,47.85 55.56,43.86 41.28,43.86 41.09,44.05 v1(40.55,44.05)
  BOTTOM w0.18: v1(40.55,44.05) 39.83,44.05 38.76,42.98 38.76,36.9 v1(39.65,36)
A0: length 38.5
  TOP w0.18: U4.15 35.81,25.58 35.88,25.64 v1(36.42,25.64) ; v1(39.29,13.47) 39.9,12.85 39.9,10.25 43.96,6.19 48.41,6.19 50.8,3.8 J4.1
  BOTTOM w0.18: v1(39.29,13.47) 39.29,17.14 39.2,17.22 39.2,19.55 39.46,19.81 39.46,21.4 36.42,24.44 v1(36.42,25.64)
A1: length 41
  TOP w0.18: v1(37.1,25.1) 36.55,25.1 36.54,25.08 U4.16 ; v1(40.45,12.64) 40.45,12.09 40.45,12.09 40.45,10.21 44.11,6.55 50.6,6.55 53.34,3.81 J4.2
  BOTTOM w0.18: v1(40.45,12.64) 40.83,13.02 40.83,13.7 40.15,14.38 40.15,16.55 40.45,16.85 40.45,17.9 39.82,18.53 39.82,21.54 37.49,23.88 37.49,24.71 v1(37.1,25.1)
A2: length 42.6
  TOP w0.18: v1(40.93,14.5) 40.93,13.96 40.92,13.95 40.92,12.93 40.99,12.86 40.99,12.53 40.99,12.53 40.99,10.17 44.17,7 52.63,7 55.88,3.75 J4.3 ; v1(38.03,24.55) 36.87,24.55 36.85,24.58 U4.17
  BOTTOM w0.18: v1(38.03,24.55) 38.03,23.85 40.18,21.69 40.18,18.72 40.93,17.97 v1(40.93,14.5)
A3: length 44.8
  TOP w0.18: J4.4 58.42,3.83 54.7,7.55 44.13,7.55 41.48,10.2 41.48,13.05 41.47,13.05 v1(41.47,13.6) ; U4.18 30.59,24.08 30.63,24.13 37.47,24.13 37.6,24 v1(38.75,24)
  BOTTOM w0.18: v1(41.47,13.6) 41.47,14.34 41.48,14.35 41.48,17.98 40.54,18.91 40.54,22.21 v1(38.75,24)
A4: length 39.6
  TOP w0.18: v1(37.4,6.55) 37.4,8.4 36.65,9.15 36.65,12.87 36.33,13.2 35.26,13.2 34.5,13.95 34.5,17.26 35.03,17.79 U4.33
  BOTTOM w0.18: v1(37.4,6.55) 37.79,6.16 57.34,6.16 J4.5
A5: length 40.9
  TOP w0.18: v1(38.8,7.09) 38.8,7.85 37.01,9.64 37.01,13.02 36.48,13.55 35.4,13.55 34.86,14.1 34.86,17.11 35.53,17.78 U4.34
  BOTTOM w0.18: v1(38.8,7.09) 39.55,7.09 39.99,6.66 59.38,6.66 J4.6
CHASSIS_USB: length 29.1
  TOP w0.3: D4.2 6.75,25.65 v1(6.75,25.59) ; C20.2 v1(2.07,20.95)
  TOP w0.4: R10.2 v3(1.62,19.05)
  BOTTOM w0.254: J5.8 1.25,31.09 ; J5.8 2.5,31.01 ; J5.8 2.5,30.03 ; J5.8 2.5,29.06 ; J5.8 1.25,28.97 ; J5.6 4.15,30.27 ; J5.6 3.25,30.27 ; J5.6 3.25,28.07 ; J5.6 3.18,29.17 ; J5.6 4.15,28.07 ; 1.25,22.25 J5.11 ; J5.11 2.5,22.33 ; J5.11 2.5,23.31 ; J5.11 2.5,24.28 ; J5.11 1.25,24.37 ; 3.25,23.07 J5.7 ; J5.7 4.15,23.07 ; J5.7 3.25,25.27 ; J5.7 3.18,24.17 ; J5.7 5.05,25.27 ; J5.7 4.15,25.27
D0: length 33
  TOP w0.18: v1(48.07,27.08) 47.98,27.16 47.26,27.16 47.17,27.08 U4.64
  BOTTOM w0.18: J2.1 48.07,35.37 v1(48.07,27.08)
D1: length 32
  TOP w0.18: U4.63 46.9,26.58 46.94,26.62 v1(47.48,26.62)
  BOTTOM w0.18: v1(47.48,26.62) 47.48,27.48 47.71,27.71 47.71,35.52 60.96,48.77 J2.2
D2: length 66.3
  TOP w0.18: J2.3 52.96,45.34 42.62,45.34 v1(42.05,44.77) ; U4.26 v1(30.83,18.83)
  BOTTOM w0.18: v1(30.83,18.83) 30.83,19.62 32.84,21.64 32.84,28.56 34.37,30.09 34.37,30.54 34.05,30.86 32.97,30.86 29.02,34.81 29.02,39.36 30.06,40.4 33.43,40.4 33.57,40.26 34.03,40.26 34.34,40.57 34.34,41.03 33.24,42.13 33.24,44.29 36,47.05 37.6,47.05 37.96,46.69 41.53,46.69 42.05,46.17 v1(42.05,44.77)
D3: length 50.7
  TOP w0.18: U4.25 34.72,20.58 34.81,20.49 v1(35.49,20.49) ; J2.4 50.84,45.76 43.49,45.76 43.11,46.14 v1(41.15,46.14)
  BOTTOM w0.18: v1(35.49,20.49) 35.88,20.88 35.88,27.18 36.6,27.9 36.6,33.53 38.4,35.33 38.4,43.39 40.76,45.76 40.77,45.76 v1(41.15,46.14)
D4: length 43.8
  TOP w0.18: v1(45.09,46.44) 46.4,47.75 50.29,47.75 J2.5 ; U4.51 46.63,20.58 v1(47,20.95)
  BOTTOM w0.18: v1(45.09,46.44) 45.09,45.66 45.5,45.25 45.5,40.26 43.16,37.92 43.16,35.29 39.99,32.11 39.99,29.88 42.07,27.8 42.07,26.34 44.51,23.9 44.51,21.64 45.2,20.95 v1(47,20.95)
D5: length 30
  TOP w0.18: J2.6 48.11,48.11 42.35,48.11 40.12,45.88 40.12,45.81 38.9,44.59 38.15,44.59 37.36,44.59 37.11,44.85 35.93,44.85 35.54,44.46 v1(34.7,44.46) ; U4.95 v1(34.03,35.62)
  BOTTOM w0.18: v1(34.7,44.46) 34.64,44.4 34.64,43.69 34.69,43.64 34.69,42.21 35.42,41.47 35.42,37.27 34.4,36.25 34.4,35.99 v1(34.03,35.62)
D6: length 28.3
  TOP w0.18: U4.96 33.53,35.35 33.49,35.39 33.49,35.84 33.67,36.02 v1(33.67,36.35) ; v1(35.5,45.21) 37.26,45.21 37.51,44.95 38.3,44.95 38.75,44.95 39.76,45.96 39.76,46.03 42.2,48.47 45.93,48.47 J2.7
  BOTTOM w0.18: v1(35.5,45.21) 34.68,45.21 34.15,44.67 34.15,43.68 34.33,43.49 34.33,42.06 35.06,41.32 35.06,40.28 34.9,40.11 34.9,37.58 v1(33.67,36.35)
D7: length 40.6
  TOP w0.18: v1(35.02,21.05) 35.04,21.05 35.04,21.04 34.24,21.04 34.2,21.08 U4.24 ; J2.8 43.82,48.9 41.93,48.9 v1(38.52,45.49)
  BOTTOM w0.18: v1(35.02,21.05) 35.52,21.54 35.52,27.33 36.24,28.05 36.24,33.68 38.03,35.48 38.03,44.46 38.52,44.95 v1(38.52,45.49)
D8: length 37.4
  TOP w0.18: U4.23 v1(34.47,21.58) ; J3.1 39.48,48.62 39.48,46.97 38.69,46.19 38.13,46.19 37.79,45.84 v1(37.79,45.51)
  BOTTOM w0.18: v1(37.79,45.51) 37.79,44.97 36.97,44.14 36.97,43.29 36.66,42.98 36.66,42.28 36.86,42.07 36.86,34.81 35.88,33.83 35.88,28.2 35.16,27.48 35.16,22.27 v1(34.47,21.58)
D9: length 30.2
  TOP w0.18: U4.4 v1(28.07,31.08) ; J3.2 39.12,47.17 38.7,46.75 37.15,46.75 36.85,46.45 v1(34.15,46.45)
  BOTTOM w0.18: v1(34.15,46.45) 32.5,46.45 31.55,45.5 31.55,44.25 30.75,43.45 29.95,43.45 28.65,42.15 28.65,40.1 28.3,39.75 28.3,36.25 27.91,35.86 27.91,33.26 27.73,33.08 27.73,32.62 28.07,32.28 v1(28.07,31.08)
D10: length 41.1
  TOP w0.18: U4.47 42.03,19.62 41.64,20.01 41.48,20.01 v1(41.09,20.4) ; J3.3 36.58,49.23 v1(38.45,47.35)
  BOTTOM w0.18: v1(38.45,47.35) 41.38,47.35 43.51,45.22 43.51,39.8 42.08,38.37 41.67,38.37 41.16,37.86 41.16,35.32 37.7,31.86 37.7,30.6 38.11,30.19 38.11,26.19 40.95,23.34 40.95,21.08 41.09,20.95 v1(41.09,20.4)
D11: length 78.8
  TOP w0.18: v1(46.58,21.59) 46.58,21.67 46.17,22.08 U4.54 ; v1(50.95,19.8) 51.34,19.41 51.53,19.41 52.35,18.59 58.74,18.59 58.76,18.57 62.26,18.57 62.43,18.4 63,18.4 69.84,25.24 69.84,26.11 68.06,27.89 J7.4
  BOTTOM w0.18: v1(50.95,19.8) 50.95,20.55 49.91,21.59 v1(46.58,21.59) 45.31,21.59 44.87,22.03 44.87,24.04 42.43,26.49 42.43,27.95 40.35,30.03 40.35,31.96 43.52,35.14 43.52,37.77 45.9,40.15 45.9,46.4 43.68,48.62 36.22,48.62 J3.4
D12: length 70.9
  TOP w0.18: v1(43.96,21.9) 43.96,21.84 44.22,21.58 U4.53 ; v1(55.45,32.75) 55.45,35.76 49.61,41.6 v1(44.85,41.6)
  BOTTOM w0.18: J7.1 63.64,31.76 61.83,33.57 58.27,33.57 57.45,32.75 v1(55.45,32.75) ; v1(43.96,21.9) 43.96,23.93 41.71,26.19 41.71,27.65 39.63,29.73 39.63,32.26 42.8,35.44 42.8,38.07 44.85,40.12 v1(44.85,41.6) 44.85,44.9 41.49,48.26 34.04,48.26 J3.5
D13: length 89.6
  TOP w0.18: v1(57.35,10.1) 56.54,10.91 47.41,10.91 45.57,12.75 45.15,13.17 45.15,17.37 45.15,19.3 v1(43.39,21.06) 43.94,21.06 43.96,21.08 U4.52
  BOTTOM w0.18: J7.3 63.64,27.07 62.42,25.85 62.42,24.27 62.6,24.1 62.6,21.92 60.94,20.26 60.94,19.68 59.78,18.51 59.78,15.07 58.51,13.8 58.51,12.35 57.35,11.2 v1(57.35,10.1) ; J3.6 31.86,47.9 41.34,47.9 43.87,45.37 43.87,39.65 42.44,38.22 42.44,35.59 39.27,32.41 39.27,29.58 41.35,27.5 41.35,26.04 43.39,23.99 v1(43.39,21.06)
JTCK: length 21.8
  TOP w0.18: v1(43.55,33.2) 43.53,33.22 U4.76
  BOTTOM w0.18: J8.4 55.01,29.16 54.95,29.22 53.17,29.22 49.67,25.71 45.74,25.71 44.23,27.23 44.23,30 43.66,30.57 43.66,32.54 43.55,32.66 v1(43.55,33.2)
JTDI: length 22.8
  TOP w0.18: U4.77 43.03,33.45 43.01,33.43 43.01,32.97 43.41,32.57 43.41,31.1 43.53,30.97 43.53,30.19 v1(43.15,29.8)
  BOTTOM w0.18: v1(43.15,29.8) 43.15,28.76 43.51,28.4 43.51,26.93 45.45,25 50.02,25 52.02,27 53.06,27 53.43,26.62 J8.8
JTDO: length 28
  TOP w0.18: v1(41.65,31.61) 40.94,31.61 40.21,32.34 37.76,32.34 37.03,33.07 U4.89
  BOTTOM w0.18: J8.6 52.39,27.89 49.85,25.36 45.59,25.36 43.87,27.08 43.87,27.38 43.87,29.85 43.15,30.57 43.15,31.85 42.75,32.25 42.21,32.25 41.65,31.69 v1(41.65,31.61)
JTMS: length 19.2
  TOP w0.18: U4.72 v1(44.23,31.08)
  BOTTOM w0.18: v1(44.23,31.08) 44.23,30.51 44.59,30.15 44.59,27.38 45.89,26.07 49.52,26.07 53.02,29.58 54.23,29.58 55.08,30.43 J8.2
LED: length 37.1
  TOP w0.18: v1(31.55,30.5) 35.32,26.73 41.06,26.73 43.91,29.58 U4.69 ; Q1.2 18.35,22.75 18.5,22.6 18.5,21.45 v1(19.3,20.65) 19.3,19.9 19.23,19.82 R8.4
  BOTTOM w0.18: v1(19.3,20.65) 20.38,20.65 30.23,30.5 v1(31.55,30.5)
LED_GOPORT1: length 38.4
  TOP w0.18: v1(54.5,21.15) 54.5,21.7 54.85,22.05 55.82,22.05 56,21.87 Q10.2 ; v1(38.15,13.4) 38.15,17.27 38.53,17.65 U4.40
  BOTTOM w0.18: v1(38.15,13.4) 38.15,11.69 41.54,8.3 49.35,8.3 54.63,13.58 54.63,15.34 53.85,16.12 53.85,18.45 54.5,19.1 v1(54.5,21.15)
LED_GOPORT2: length 41.9
  TOP w0.18: v1(39.24,12.65) 38.7,13.2 38.7,13.63 38.51,13.81 38.51,16.98 39.53,18 U4.42 ; Q11.5 56,29.38 55.84,29.22 54.5,29.22 54.12,28.84 54.12,25.82 53.26,24.96 53.26,22.59 v1(53.65,22.2)
  BOTTOM w0.18: v1(53.65,22.2) 53.65,18.8 53.49,18.64 53.49,15.58 54,15.07 54,13.68 53.34,13.02 50.73,13.02 50.23,13.52 47.55,13.52 45.72,11.7 40.19,11.7 v1(39.24,12.65)
LED_GOPORT3: length 44.8
  TOP w0.18: Q11.2 56,26.65 57.5,25.15 v1(57.5,24.5) ; U4.45 41.03,17.96 42.05,16.94 42.05,15.17 42.2,15.02 42.73,14.49 42.73,14.12 42.73,11.1 44.82,9.01 55.03,9.01 v1(55.91,9.89)
  BOTTOM w0.18: v1(55.91,9.89) 56.49,10.46 56.49,11.1 58.15,12.76 58.15,13.95 59.42,15.22 59.42,18.66 60.58,19.83 60.58,20.83 58.2,23.22 58.2,23.8 v1(57.5,24.5)
OSC_IN: length 9
  TOP w0.2: Y1.3 23.8,28.45 25.17,27.08 U4.12
  TOP w0.3: Y1.3 24.2,29.15 C18.1
OSC_OUT: length 2
  TOP w0.2: R7.2 28.25,26.3 28.53,26.58 U4.13
OTG_FS_DM: length 2.1
  TOP w0.18: U4.70 46.3,30.08 46.36,30.02 47.4,30.02
OTG_FS_DP: length 2.2
  TOP w0.18: U4.71 46.27,30.58 46.36,30.68 R9.3
PWR_LED: length 18.2
  TOP w0.18: Q1.5 v1(20.95,22.75) 20.95,21.85 20.5,21.4 20.5,19.5 20.09,19.1 19.18,19.1 R8.3
  TOP w0.2: U4.7 28.93,29.58 28.35,29 v1(27.6,29)
  BOTTOM w0.2: v1(27.6,29) 21.35,22.75 v1(20.95,22.75)
PWR_ON_GOPORT1: length 34.5
  TOP w0.18: U4.88 37.53,33.08 37.9,32.71 41.09,32.71 v1(41.48,32.32) ; v1(53.4,14.9) 54.2,15.7 55.82,15.7 56,15.88 Q6.5
  BOTTOM w0.18: v1(41.48,32.32) 40.95,31.79 40.95,29.94 42.79,28.1 42.79,26.64 45.88,23.55 50.35,23.55 52.51,21.39 52.51,19.52 53,19.03 53,15.3 v1(53.4,14.9)
PWR_ON_GOPORT2: length 19.5
  TOP w0.18: v1(53.45,13.9) 54.89,15.34 55.78,15.34 56,15.12 Q6.2 ; U4.57 46.62,23.58 46.78,23.42 46.78,23.39 v1(47.16,23)
  BOTTOM w0.18: v1(47.16,23) 50.3,23 52.15,21.15 52.15,19.38 52.64,18.88 52.64,14.71 v1(53.45,13.9)
PWR_ON_GOPORT3: length 12.7
  TOP w0.18: U4.59 46.15,24.58 46.28,24.45 v1(47.5,24.45) ; v1(54.4,24.6) 55.4,24.6 56,24 Q10.5
  BOTTOM w0.18: v1(47.5,24.45) 50.03,24.45 51.13,25.55 52.91,25.55 53.85,24.6 v1(54.4,24.6)
SCL: length 31.5
  TOP w0.18: U4.92 v1(35.53,35.39) ; v1(36.2,45.85) 32.2,45.85 29.92,48.13 28.09,48.13 27.62,48.6 21,48.6 J3.10
  BOTTOM w0.18: v1(36.2,45.85) 36.2,44.63 35.88,44.3 35.88,42.04 36.14,41.77 36.14,36 v1(35.53,35.39)
SDA: length 31.8
  TOP w0.18: v1(27.5,36.4) 28.09,35.8 28.09,35.16 29.56,33.7 30.71,33.7 31.16,33.25 32.4,33.25 33,32.65 34.22,32.65 35.03,33.46 U4.93 ; v1(28.2,49.45) 26.55,49.45 26.11,49.01 23.12,49.01 J3.9
  BOTTOM w0.18: v1(27.5,36.4) 27.94,36.84 27.94,40.14 28.2,40.4 v1(28.2,49.45)
SPI3_MISO: length 33.3
  TOP w0.18: U4.79 42.03,33.44 43.05,32.42 43.05,30.47 42.6,30.03 42.6,30 41.46,28.86 39.31,28.86 38.9,28.45 36.24,28.45 34.37,30.32 v1(33.83,30.32) ; v1(26.8,17.7) 26.3,17.2 R5.4
  BOTTOM w0.18: v1(26.8,17.7) 27.52,18.42 27.52,25.72 31.25,29.45 32.96,29.45 v1(33.83,30.32)
SPI4_MISO: length 84.9
  TOP w0.18: U4.44 40.53,17.95 41.69,16.79 41.69,15.02 41.84,14.88 41.84,14.87 42.37,14.34 42.37,13.98 42.37,10.95 44.67,8.65 63.3,8.65 65.95,11.3 v1(66.85,11.3) ; J12.8 75.87,41.9 74.53,41.9 74.35,41.72 v1(74.35,39.65) ; v1(74.25,8.82) J10.8 ; v1(74.19,25.4) J11.8
  BOTTOM w0.18: 74.25,10.74 76.85,13.35 76.85,19.7 74.19,22.36 v1(74.19,25.4) 74.19,28 76.5,30.3 76.5,36.35 74.35,38.5 v1(74.35,39.65) ; 74.25,10.74 v1(74.25,8.82) ; 74.25,10.74 73.66,10.74 73.1,11.3 v1(66.85,11.3)
SPI4_MOSI: length 88.8
  TOP w0.18: J12.7 70.38,41.98 69.76,41.36 69.76,27.93 69.75,27.93 69.75,27.47 69.76,27.47 69.76,26.79 70.2,26.35 70.2,25.4 ; v1(40.75,27.28) 35.28,27.28 32.09,30.46 32.09,30.73 31.78,31.05 31.32,31.05 30.86,30.58 U4.5 ; 70.2,25.4 70.2,19.46 v1(69.67,18.93) 67.03,18.93 66.14,18.04 62.28,18.04 62.12,18.21 57.37,18.21 57.35,18.23 52.17,18.23 51.4,19 v1(50.85,19) ; 70.2,25.4 J11.7 ; J10.7 70.08,8.82 68.75,10.15 v1(68.75,14.7)
  BOTTOM w0.18: v1(68.75,14.7) 69.67,15.62 v1(69.67,18.93) ; v1(40.75,27.28) 40.75,26.73 40.75,26.73 40.75,26.12 42.77,24.11 42.77,20.91 43.22,20.46 46.31,20.46 47.77,19 v1(50.85,19)
SPI4_SCK: length 90.4
  TOP w0.18: 73.65,24.13 J11.9 ; 73.65,24.13 73.65,30.45 71.8,32.3 71.8,39.81 72.05,40.06 J12.9 ; 73.65,24.13 73.65,23.1 71.5,20.95 71.5,18.38 ; J10.9 73.52,7.55 73.7,7.73 73.7,13.95 71.5,16.15 71.5,18.38 ; v1(39.44,28) 38.89,28 38.89,28 35.37,28 33.28,30.09 33.28,31.31 32.1,32.49 30.74,32.49 30.65,32.58 U4.1 ; 71.5,18.38 67.18,18.38 66.48,17.68 62.14,17.68 61.97,17.85 57.22,17.85 57.2,17.87 51.79,17.87 51.39,18.27 v1(50.84,18.27)
  BOTTOM w0.18: v1(39.44,28) 39.45,28 39.45,26.92 42.41,23.96 42.41,21.1 42.41,20.76 43.07,20.1 46.16,20.1 47.99,18.27 v1(50.84,18.27)
SWITCH1: length 69.4
  TOP w0.18: SW1.4 13.48,48.62 14.77,47.34 29.61,47.34 33.03,43.92 34.64,43.92 35.19,43.91 35.19,43.91 v1(35.19,43.91) ; v1(41.34,24.24) 43.11,24.24 43.27,24.08 U4.58 ; v1(38.71,31.59) 38.16,31.59 38.1,31.65 37.65,31.65 36.03,33.27 U4.91 36.03,35.11 36.08,35.16 36.08,35.61 35.69,36 v1(34.95,36) 34.58,35.63 34.58,35.39 34.53,35.35 U4.94 ; R12.1 v1(49.62,14.7)
  BOTTOM w0.18: v1(38.71,31.59) 38.71,30.89 38.83,30.77 38.83,26.75 v1(41.34,24.24) 42.05,23.52 42.05,21.25 42.05,20.61 47.96,14.7 v1(49.62,14.7) ; v1(34.95,36) 35.78,36.83 35.78,41.62 35.19,42.22 v1(35.19,43.91)
USART3_RX_GOPORT1: length 46.2
  TOP w0.18: U4.56 46.31,23.08 46.94,22.45 47.1,22.45 47.91,21.65 47.91,20.01 45.87,17.97 45.87,17.67 45.87,13.47 47.52,11.82 59.84,11.82 60.14,11.82 61.41,10.54 62.75,10.54 62.75,10.55 63.13,10.55 63.66,11.08 63.66,11.34 66.92,14.6 66.92,14.71 67.46,15.25 68.97,15.25 69.5,14.72 69.5,10.85 70.26,10.09 J10.5
USART3_TX_GOPORT1: length 74.9
  TOP w0.18: R1.7 40.75,39.1 v1(40.9,38.95) ; J10.4 74.63,11.36 74.45,11.54 v1(74.45,15.2) ; v1(40.33,23.2) 40.94,22.58 U4.55 46.3,22.58 46.79,22.09 46.95,22.09 47.55,21.5 47.55,20.16 45.51,18.12 45.51,17.52 45.51,13.32 45.72,13.11 47.38,11.46 59.99,11.46 61.05,10.4 61.26,10.19 63.17,10.19 63.17,10.19 63.27,10.19 64.02,10.93 64.02,11.04 v1(67.47,14.48)
  BOTTOM w0.18: v1(40.9,38.95) 40.44,38.49 40.44,35.62 39.86,35.04 36.98,32.16 36.98,28.92 37.33,28.57 37.43,28.57 37.7,28.3 37.7,25.82 v1(40.33,23.2) ; v1(67.47,14.48) 68.01,14.48 68.34,14.15 68.98,14.15 70.02,15.2 v1(74.45,15.2)
USART7_RX_GOPORT2: length 57.8
  TOP w0.18: J11.5 70.58,26.67 70.3,26.95 v1(70.3,27.7) ; U4.38 37.53,17.96 37.55,17.95 v1(37.55,14.04) ; v1(57.9,20.85) 57.9,22.25 58.88,23.23 58.88,24.07 59.53,24.72 61.73,24.72 62.31,24.14 67.63,24.14 v1(69.3,25.8)
  BOTTOM w0.18: v1(57.9,20.85) 57.07,20.02 57.07,15.47 57.06,15.46 56.74,15.14 55.9,14.29 55.9,13.55 55.58,13.23 54.83,13.23 49.34,7.74 41.59,7.74 37.55,11.78 v1(37.55,14.04) ; v1(70.3,27.7) 70.3,26.8 v1(69.3,25.8)
USART7_TX_GOPORT2: length 92.7
  TOP w0.18: v1(41.9,37.82) 41.35,37.82 41.25,37.93 40.86,37.93 40.25,38.54 R1.6 ; J11.4 74.78,27.94 74.37,28.35 74.37,31.01 v1(73.99,31.39) ; v1(59,10) 58.5,9.5 57.07,9.5 56.02,10.55 47.56,10.55 47.56,10.55 47.26,10.55 45.42,12.39 44.79,13.02 44.79,18.86 43.7,19.95 43.31,19.95 v1(41.49,21.76) 40.09,21.76 40,21.85 36.65,21.85 36.35,21.55 36.35,20.82 36.87,20.3 37.18,20.3 37.78,19.7 37.85,19.7 38.03,19.52 U4.39
  BOTTOM w0.18: v1(41.9,37.82) 41.9,37.28 41.9,35.55 38.06,31.71 38.06,30.84 38.47,30.43 38.47,26.34 41.49,23.31 v1(41.49,21.76) ; v1(73.99,31.39) 71.54,31.39 67.63,27.48 67.63,24.95 65.52,22.84 64.54,22.84 64,22.84 63.58,22.42 63.58,21.88 61.66,19.96 61.66,19.38 60.5,18.21 60.5,14.75 60.36,14.61 60.36,12.62 59,11.26 v1(59,10)
USART8_RX_GOPORT3: length 51.3
  TOP w0.18: v1(33.88,33.28) 33.21,33.28 33.03,33.46 U4.97 ; J12.5 68.85,43.25 67.1,45 57.55,45 56.05,43.5 40.05,43.5 39.68,43.87 39.2,43.87 37.85,43.87 37.85,43.87 37.07,43.87 37,43.94 v1(36.42,43.94)
  BOTTOM w0.18: v1(33.88,33.28) 34.68,33.28 36.5,35.1 36.5,41.92 36.3,42.13 36.3,43.27 36.42,43.4 v1(36.42,43.94)
USART8_TX_GOPORT3: length 63.9
  TOP w0.18: R1.5 39.5,39.95 38.6,39.95 37.55,38.9 v1(34.35,38.9) ; v1(32.99,36.06) 32.99,35.56 32.53,35.11 U4.98 ; v1(33.78,42.95) 35,42.95 35.73,43.69 35.73,44.14 36.08,44.49 36.96,44.49 37.21,44.23 38,44.23 39.05,44.23 39.41,44.59 41.05,44.59 41.42,44.22 55.02,44.22 59.01,48.21 72.95,48.21 73.25,48.21 74.16,47.3 74.16,44.84 74.48,44.52 J12.4
  BOTTOM w0.18: v1(33.78,42.95) 33.78,42.09 34.7,41.17 34.7,40.42 34.35,40.07 v1(34.35,38.9) 34.35,37.85 32.99,36.49 v1(32.99,36.06)
USB5V: length 4.4
  TOP w0.3: D4.5 6.75,28.23 6.65,28.32
  TOP w0.4: J5.1 5.57,27.97 5.92,28.32 6.65,28.32 F1.1
USB5V_F: length 69.9
  TOP w0.18: v1(44.24,37.49) 43.64,37.49 43.42,37.27 34.61,37.27 33.46,38.42 27.42,38.42 25.92,36.92 23.12,36.92 22.82,36.92 21.18,35.28 21.18,26.29 20.71,25.82 17,25.82 15.28,27.54 9.38,27.54 7.9,29.02 7.9,32.4 ; v1(46.7,29.08) U4.68
  TOP w0.8: Q3.3 11.5,32.25 10.75,33 8.5,33 7.9,32.4 F1.2
  BOTTOM w0.18: v1(44.24,37.49) 44.63,37.1 44.63,36.98 46.7,34.91 v1(46.7,29.08)
USB_D+: length 67.3
  TOP w0.18: R9.2 49.67,30.68 49.82,30.53 50.02,30.53 50.95,31.45 50.95,35.3 49.7,36.55 34.91,36.55 34.31,36.55 33.16,37.7 27.72,37.7 26.22,36.2 23.12,36.2 21.9,34.98 21.9,25.99 21.01,25.1 20.71,25.1 16.7,25.1 16.49,25.31 14.98,26.82 9.2,26.82 9.05,26.67 9.05,26.2 8.95,26.1 8.65,26.1 8.55,26.2 8.55,26.65 8.38,26.82 6.25,26.82 ; J5.3 5.12,26.67 5.27,26.82 6.25,26.82 ; 6.25,26.82 D4.1
USB_D-: length 67.4
  TOP w0.18: J5.2 5.13,27.32 5.27,27.18 6.25,27.18 ; 6.25,27.18 15.13,27.18 16.85,25.46 20.86,25.46 21.54,26.14 21.54,35.13 22.97,36.56 26.07,36.56 27.57,38.06 33.31,38.06 34.46,36.91 34.76,36.91 49.55,36.91 49.55,36.91 49.85,36.91 51.31,35.45 51.31,31.3 50.17,30.17 49.82,30.17 49.67,30.02 48.6,30.02 ; 6.25,27.18 D4.6
VCAP_1: length 2.7
  TOP w0.3: C17.1 43.5,17.11 43.03,17.57 U4.49
VCAP_2: length 4.7
  TOP w0.3: U4.73 48.41,31.58 49,32.17 C16.1
N62667: length 6.3
  TOP w0.2: 18.59,31.9 U3.1 ; 18.59,31.9 19.22,32.53 19.22,33.73 R6.2 ; 18.59,31.9 18.59,30.07 17.95,29.43 R4.1
N62753: length 14.3
  TOP w0.18: 22.5,17.9 Q2.2 ; 22.5,17.9 22.84,18.25 28.02,18.25 28.17,18.39 28.62,18.39 28.94,18.07 28.94,17.81 29.35,17.4 29.35,14.85 29.2,14.7 R5.8 ; 22.5,17.9 22.05,17.9 21.85,17.7 Q2.3
N62779: length 2.9
  TOP w0.5: U1.5 26.18,41.9 L1.1
N62801: length 22.2
  TOP w0.2: R1.1 41.5,41.55 43.95,41.55 44.6,42.2 61.4,42.2 61.76,42.56 D2.C
N62841: length 12.4
  TOP w0.18: v1(37,17.7) 37,18.1 37.03,18.13 U4.37 ; v1(28.4,17.84) 27.67,17.84 27.36,17.53 27.36,17.48 27.1,17.23 R5.3
  BOTTOM w0.18: v1(37,17.7) 36.45,17.7 36.31,17.84 30.02,17.84 29.88,17.7 29.42,17.7 29.28,17.84 v1(28.4,17.84)
N63081: length 8.4
  TOP w0.3: 28.7,22.08 28.7,22.37 28.91,22.58 U4.21 ; 28.7,22.08 U4.22 ; 28.7,22.08 28.53,22.08 28,21.55 C5.1
  TOP w0.6: L2.1 C44.1 26.35,20.8 C5.1
N74908: length 44.7
  TOP w0.18: Q1.6 20.25,23.4 22.26,25.41 22.26,34.83 23.27,35.84 26.91,35.84 29.41,33.34 30.56,33.34 31.01,32.89 32.21,32.89 34.42,30.68 34.52,30.68 36.09,29.1 37.01,29.1 37.02,29.11 v1(37.56,29.11) ; v1(41.7,38.95) 41.3,39.35 R1.8
  BOTTOM w0.18: v1(41.7,38.95) 40.8,38.05 40.8,35.47 40.01,34.68 37.34,32.01 37.34,29.88 37.56,29.66 v1(37.56,29.11)
N77511: length 10.1
  TOP w0.18: D1.C 12.1,20 17.4,14.7 R3.1
N77515: length 9.1
  TOP w0.18: R3.2 17.2,16.3 15.75,17.75 15.75,21.35 16.5,22.1 Q1.3
N197515: length 7.4
  TOP w0.18: R15.8 50.7,24.35 v1(51.25,24.9) ; v1(54.17,23.91) 55.21,23.91 55.35,23.77 Q10.6
  BOTTOM w0.18: v1(54.17,23.91) 53.59,23.91 52.6,24.9 v1(51.25,24.9)
N197535: length 40.2
  TOP w0.18: R15.1 50.7,21.09 50.3,20.69 50.3,18 50.74,17.56 51.07,17.56 51.13,17.5 51.92,17.5 51.93,17.51 57.05,17.51 57.07,17.49 61.82,17.49 64.3,15.01 64.3,13 v1(62.75,11.45) ; v1(71.55,2.55) D5.C
  BOTTOM w0.18: v1(71.55,2.55) 70.95,3.15 66.2,3.15 62.75,6.6 62.75,10.9 62.75,10.91 v1(62.75,11.45)
N197921: length 16.7
  TOP w0.18: Q11.3 56.65,28.15 57.17,28.67 57.17,31.73 56.9,32 55.25,32 53.59,30.34 53.59,29.33 53.4,29.14 53.4,26.27 51.25,24.12 R15.7
N197949: length 25.5
  TOP w0.18: R15.2 51.25,20.5 51.51,20.25 52.73,20.25 52.77,20.3 53.29,20.3 54.13,19.45 58.89,19.45 59.06,19.29 59.95,19.29 60.38,19.72 v1(62.66,19.72)
  TOP w0.25: D6.C v1(73.2,18.2)
  BOTTOM w0.18: v1(73.2,18.2) 71.57,19.83 69.29,19.83 69.18,19.72 v1(62.66,19.72)
N198166: length 9.1
  TOP w0.18: Q11.6 54.45,29.95 53.95,29.45 53.95,29.18 53.76,28.99 53.76,26.12 51.75,24.11 R15.6
N198194: length 43.3
  TOP w0.18: R15.3 51.75,20.98 52.08,20.66 53.3,20.66 53.88,21.23 53.88,21.66 54.2,21.98 54.2,23.11 53.62,23.68 53.62,24.59 54.17,25.14 56.08,25.14 57.27,23.95 57.74,23.95 58.1,24.31 58.1,25.3 57.53,25.87 57.53,31.88 57.09,32.32 57.09,35.89 59.85,38.65 v1(67.65,38.65)
  TOP w0.25: v1(72.6,37.4) 73.2,36.8 D7.C
  BOTTOM w0.18: v1(67.65,38.65) 71.35,38.65 v1(72.6,37.4)
